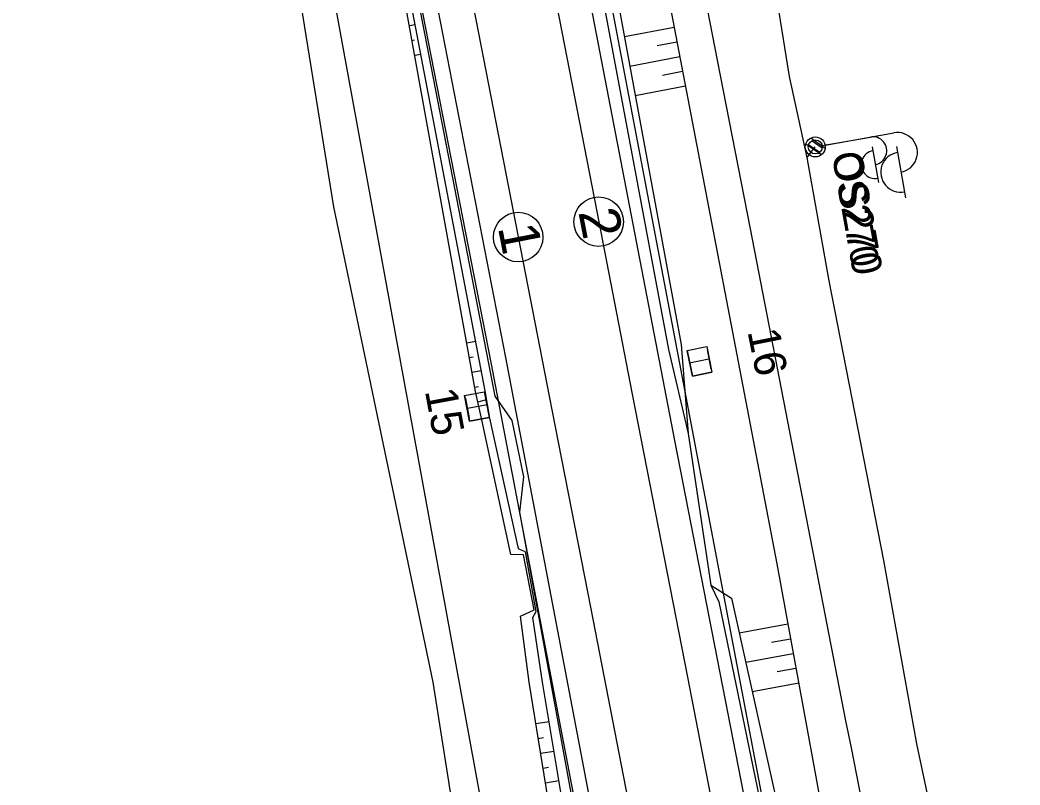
# Model space of a CAD drawing. Extents: x -545967 to -545044, y -1122650 to -1118491.
# Drawn here: x -545852.1 to -545802.1, y -1118662.4 to -1118624.1 of the extents above; entities that cross this region are included whole.
import ezdxf

# ---------------------------------------------------------------- set-up
doc = ezdxf.new("R2010")
doc.units = 0
for name, color, linetype in [('Vrstva 1', 7, 'Continuous'), ('Vrstva 1 - Koleje', 7, 'Continuous'), ('Vrstva 11 - Trakce', 7, 'Continuous'), ('Vrstva 12 - Trakce zaklady', 7, 'Continuous'), ('Vrstva 25', 7, 'Continuous'), ('Vrstva 25 - silnoproud prvky', 7, 'Continuous'), ('Vrstva 26', 7, 'Continuous'), ('Vrstva 26 - silnoproud', 7, 'Continuous'), ('Vrstva 28 - zabzar', 7, 'Continuous'), ('Vrstva 32', 7, 'Continuous'), ('Vrstva 4 - Teren - stezky - prechody - plochy', 7, 'Continuous'), ('Vrstva 44', 7, 'Continuous'), ('Vrstva 48', 7, 'Continuous'), ('Vrstva 49', 7, 'Continuous')]:
    doc.layers.add(name, color=color, linetype=linetype)

msp = doc.modelspace()

# ---------------------------------------------------------------- linework, layer by layer
at = {"layer": 'Vrstva 1'}
msp.add_lwpolyline([(-545825.931, -1118581.521), (-545824.016, -1118591.357), (-545817.098, -1118626.815), (-545815.58, -1118634.584), (-545810.799, -1118659.197), (-545810.531, -1118660.549), (-545805.871, -1118684.414), (-545803.343, -1118697.361)], dxfattribs=at)
at = {"layer": 'Vrstva 1 - Koleje'}
for points in [[(-545844.611, -1118524.236), (-545843.323, -1118530.854), (-545841.995, -1118537.671), (-545840.062, -1118547.589), (-545838.151, -1118557.387), (-545836.187, -1118567.479), (-545834.293, -1118577.171), (-545832.142, -1118588.194), (-545830.344, -1118597.44), (-545828.848, -1118605.077), (-545828.138, -1118608.718), (-545827.12, -1118613.935), (-545825.269, -1118623.436), (-545823.266, -1118633.717), (-545821.486, -1118642.857), (-545818.722, -1118657.024), (-545817.482, -1118663.386), (-545815.845, -1118671.798), (-545813.797, -1118682.286), (-545811.996, -1118691.52), (-545809.67, -1118703.454), (-545807.882, -1118712.632)], [(-545848.628, -1118525.023), (-545847.323, -1118531.712), (-545846.098, -1118538.003), (-545844.166, -1118547.957), (-545842.342, -1118557.292), (-545840.544, -1118566.52), (-545838.785, -1118575.544), (-545836.613, -1118586.684), (-545834.863, -1118595.653), (-545833.089, -1118604.755), (-545832.153, -1118609.557), (-545831.329, -1118613.781), (-545829.452, -1118623.418), (-545827.682, -1118632.501), (-545825.51, -1118643.639), (-545823.563, -1118653.595), (-545821.825, -1118662.539), (-545819.916, -1118672.31), (-545817.993, -1118682.172), (-545816.178, -1118691.474), (-545814.43, -1118700.429), (-545812.52, -1118710.222), (-545810.747, -1118719.317)]]:
    msp.add_lwpolyline(points, dxfattribs=at)
for centre in [(-545823.168, -1118634.223), (-545827.196, -1118634.992)]:
    msp.add_circle(centre, 1.239, dxfattribs=at)
at = {"layer": 'Vrstva 11 - Trakce'}
for p, q in [((-545818.72, -1118640.815), (-545818.524, -1118641.795)), ((-545817.74, -1118640.619), (-545817.544, -1118641.599)), ((-545817.642, -1118641.109), (-545818.622, -1118641.305)), ((-545828.845, -1118642.892), (-545828.662, -1118643.875)), ((-545829.828, -1118643.075), (-545829.645, -1118644.058)), ((-545828.753, -1118643.384), (-545829.737, -1118643.566))]:
    msp.add_line(p, q, dxfattribs=at)
at = {"layer": 'Vrstva 12 - Trakce zaklady'}
for p, q in [((-545818.73, -1118640.671), (-545817.749, -1118640.475)), ((-545818.474, -1118641.954), (-545817.493, -1118641.758)), ((-545829.877, -1118642.92), (-545828.894, -1118642.738))]:
    msp.add_line(p, q, dxfattribs=at)
for points in [[(-545818.474, -1118641.954), (-545818.73, -1118640.671), (-545817.749, -1118640.475), (-545817.493, -1118641.758), (-545818.474, -1118641.954)], [(-545818.73, -1118640.671), (-545818.73, -1118640.671), (-545818.474, -1118641.954), (-545818.474, -1118641.954)], [(-545828.894, -1118642.738), (-545828.655, -1118644.026), (-545829.638, -1118644.208), (-545829.877, -1118642.92), (-545828.894, -1118642.738)], [(-545829.877, -1118642.92), (-545829.877, -1118642.92), (-545829.638, -1118644.208)], [(-545828.894, -1118642.738), (-545828.894, -1118642.738), (-545828.655, -1118644.026), (-545828.655, -1118644.026)], [(-545829.638, -1118644.208), (-545829.638, -1118644.208), (-545828.655, -1118644.026)]]:
    msp.add_lwpolyline(points, dxfattribs=at)
at = {"layer": 'Vrstva 25'}
for p, q in [((-545811.827, -1118630.39), (-545808.382, -1118629.773)), ((-545812.791, -1118630.32), (-545812.006, -1118630.867)), ((-545812.547, -1118630.033), (-545811.825, -1118630.536)), ((-545808.258, -1118630.462), (-545807.8, -1118633.021))]:
    msp.add_line(p, q, dxfattribs=at)
msp.add_circle((-545812.319, -1118630.478), 0.5, dxfattribs=at)
msp.add_circle((-545812.319, -1118630.478), 0.5, dxfattribs=at)
for centre, start, end in [((-545808.205, -1118630.757), 280.1559, 100.1559), ((-545808.041, -1118631.744), 99.4533, 280.8585)]:
    msp.add_arc(centre, 1, start, end, dxfattribs=at)
at = {"layer": 'Vrstva 25 - silnoproud prvky'}
for p, q in [((-545811.974, -1118630.416), (-545809.563, -1118629.984)), ((-545812.65, -1118630.367), (-545812.1, -1118630.75)), ((-545812.479, -1118630.167), (-545811.973, -1118630.518)), ((-545809.476, -1118630.467), (-545809.156, -1118632.258))]:
    msp.add_line(p, q, dxfattribs=at)
msp.add_circle((-545812.319, -1118630.478), 0.35, dxfattribs=at)
for centre, start, end in [((-545809.439, -1118630.673), 280.1559, 100.1559), ((-545809.324, -1118631.364), 99.4533, 280.8585)]:
    msp.add_arc(centre, 0.7, start, end, dxfattribs=at)
at = {"layer": 'Vrstva 26'}
for points in [[(-545795.14, -1118719.856), (-545797.401, -1118709.038), (-545800.896, -1118690.8), (-545801.851, -1118685.761), (-545802.818, -1118681.484), (-545803.86, -1118675.25), (-545805.172, -1118668.631), (-545806.131, -1118665.54), (-545807.231, -1118660.35), (-545808.894, -1118651.177), (-545811.62, -1118637.176), (-545812.724, -1118631.013), (-545813.605, -1118626.947), (-545815.439, -1118615.53)], [(-545812.724, -1118631.013), (-545812.319, -1118630.478)]]:
    msp.add_lwpolyline(points, dxfattribs=at)
at = {"layer": 'Vrstva 26 - silnoproud'}
for points in [[(-545795.14, -1118719.856), (-545797.401, -1118709.038), (-545800.896, -1118690.8), (-545801.851, -1118685.761), (-545802.818, -1118681.484), (-545803.86, -1118675.25), (-545805.172, -1118668.631), (-545806.131, -1118665.54), (-545807.231, -1118660.35), (-545808.894, -1118651.177), (-545811.62, -1118637.176), (-545812.724, -1118631.013), (-545813.605, -1118626.947), (-545815.439, -1118615.53)], [(-545812.724, -1118631.013), (-545812.319, -1118630.478)]]:
    msp.add_lwpolyline(points, dxfattribs=at)
at = {"layer": 'Vrstva 28 - zabzar'}
msp.add_lwpolyline([(-545825.23, -1118696.09), (-545825.619, -1118693.585), (-545825.984, -1118691.226), (-545826.08, -1118690.61), (-545827.72, -1118683.66), (-545828.55, -1118678.72), (-545828.78, -1118674.2), (-545831.46, -1118657.27), (-545836.43, -1118633.48), (-545838.77, -1118619), (-545839.17, -1118613.92), (-545839.25, -1118611.04), (-545838.43, -1118605.08), (-545838.36, -1118603.32)], dxfattribs=at)
at = {"layer": 'Vrstva 32'}
msp.add_lwpolyline([(-545820.43, -1118719.58), (-545822.89, -1118707.67), (-545825.23, -1118696.09), (-545826.08, -1118690.61), (-545827.72, -1118683.66), (-545828.55, -1118678.72), (-545828.78, -1118674.2), (-545831.46, -1118657.27), (-545836.43, -1118633.48), (-545838.77, -1118619)], dxfattribs=at)
at = {"layer": 'Vrstva 4 - Teren - stezky - prechody - plochy'}
for points in [[(-545842.057, -1118523.737), (-545841.08, -1118528.803), (-545840.285, -1118532.869), (-545839.902, -1118534.493), (-545835.95, -1118554.692), (-545830.173, -1118584.852), (-545827.402, -1118599.381), (-545819.669, -1118640.626), (-545818.68, -1118644.829), (-545817.556, -1118652.409), (-545817.153, -1118653.253), (-545814.795, -1118664.646), (-545810.716, -1118686.202), (-545798.466, -1118747.292), (-545787.709, -1118802.92), (-545777.141, -1118857.583)], [(-545842.991, -1118523.919), (-545841.705, -1118530.396), (-545836.849, -1118554.447), (-545831.054, -1118584.604), (-545819.351, -1118645.264), (-545811.232, -1118686.911), (-545799.532, -1118746.647), (-545788.535, -1118802.768), (-545777.847, -1118857.696), (-545765.826, -1118919.341), (-545755.98, -1118970.183), (-545745.509, -1119023.121), (-545734.813, -1119078.883), (-545723.148, -1119138.675), (-545711.327, -1119199.256), (-545707.51, -1119218.932), (-545706.355, -1119218.803)], [(-545711.324, -1119247.435), (-545711.901, -1119243.963), (-545720.224, -1119201.665), (-545721.285, -1119195.757), (-545731.546, -1119141.712), (-545737.081, -1119112.42), (-545743.441, -1119079.103), (-545754.278, -1119022.005), (-545764.127, -1118971.243), (-545774.702, -1118917.119), (-545786.098, -1118858.181), (-545797.005, -1118803.413), (-545807.661, -1118749.422), (-545819.911, -1118686.431), (-545828.531, -1118641.36), (-545850.15, -1118530.525), (-545851.156, -1118525.517)], [(-545710.225, -1119247.22), (-545719.004, -1119201.386), (-545730.622, -1119141.385), (-545736.208, -1119112.206), (-545742.564, -1119078.927), (-545753.414, -1119021.814), (-545763.359, -1118970.942), (-545773.922, -1118916.709), (-545785.328, -1118858.188), (-545796.206, -1118802.914), (-545806.845, -1118748.63), (-545819.206, -1118686.191), (-545827.818, -1118641.013), (-545849.345, -1118530.249), (-545850.409, -1118525.371)]]:
    msp.add_lwpolyline(points, dxfattribs=at)
at = {"layer": 'Vrstva 44'}
for points in [[(-545846.223, -1118571.979), (-545846.221, -1118572.119), (-545836.892, -1118620.467), (-545827.979, -1118669.157), (-545827.809, -1118669.462), (-545827.871, -1118669.728), (-545818.616, -1118716.33), (-545818.55, -1118716.796), (-545818.473, -1118717.196), (-545808.913, -1118765.432), (-545808.826, -1118765.882), (-545808.745, -1118766.383), (-545799.375, -1118814.752), (-545799.301, -1118815.001), (-545799.29, -1118815.321), (-545789.933, -1118863.748)], [(-545823.989, -1118615.966), (-545823.909, -1118616.115), (-545814.588, -1118665.112), (-545823.538, -1118666.512), (-545823.785, -1118666.525)], [(-545833.154, -1118618.242), (-545828.365, -1118642.955), (-545827.522, -1118644.179), (-545826.938, -1118646.983), (-545827.134, -1118648.756), (-545823.92, -1118666.279), (-545823.785, -1118666.525)]]:
    msp.add_lwpolyline(points, dxfattribs=at)
at = {"layer": 'Vrstva 48'}
for p, q in [((-545832.646, -1118624.41), (-545832.358, -1118624.358)), ((-545819.385, -1118624.497), (-545821.877, -1118624.973)), ((-545832.513, -1118625.148), (-545832.394, -1118625.127)), ((-545819.245, -1118625.234), (-545820.243, -1118625.425)), ((-545832.379, -1118625.886), (-545832.076, -1118625.831)), ((-545819.104, -1118625.97), (-545821.604, -1118626.449)), ((-545818.963, -1118626.707), (-545819.965, -1118626.899)), ((-545818.822, -1118627.444), (-545821.332, -1118627.924)), ((-545829.777, -1118640.284), (-545829.322, -1118640.202)), ((-545829.643, -1118641.022), (-545829.458, -1118640.988)), ((-545829.51, -1118641.76), (-545829.04, -1118641.675)), ((-545829.377, -1118642.498), (-545829.185, -1118642.463)), ((-545829.219, -1118643.231), (-545828.772, -1118643.128)), ((-545813.695, -1118654.369), (-545816.125, -1118654.816)), ((-545813.56, -1118655.107), (-545814.52, -1118655.284)), ((-545813.424, -1118655.844), (-545815.799, -1118656.282)), ((-545813.288, -1118656.582), (-545814.227, -1118656.755)), ((-545813.152, -1118657.319), (-545815.473, -1118657.747)), ((-545826.312, -1118659.344), (-545825.649, -1118659.237)), ((-545826.192, -1118660.085), (-545825.925, -1118660.042)), ((-545826.072, -1118660.825), (-545825.402, -1118660.717)), ((-545825.952, -1118661.565), (-545825.683, -1118661.522)), ((-545825.833, -1118662.306), (-545825.154, -1118662.196))]:
    msp.add_line(p, q, dxfattribs=at)
at = {"layer": 'Vrstva 49'}
for points in [[(-545839.308, -1118523.198), (-545838.102, -1118529.579), (-545837.4, -1118533.485), (-545832.706, -1118555.695), (-545825.144, -1118594.377), (-545814.251, -1118651.352), (-545808.026, -1118685.152), (-545795.162, -1118750.192), (-545783.943, -1118809.71), (-545774.848, -1118856.951), (-545763.418, -1118915.038), (-545752.928, -1118968.655), (-545741.707, -1119025.946), (-545730.219, -1119081.986), (-545719.001, -1119141.326), (-545708.857, -1119196.833), (-545704.642, -1119214.146)], [(-545841.458, -1118523.619), (-545840.502, -1118528.796), (-545840.206, -1118530.169), (-545839.525, -1118532.718), (-545839.264, -1118534.264), (-545835.124, -1118554.723), (-545829.514, -1118584.885), (-545827.92, -1118592.873), (-545827.648, -1118594.262), (-545826.635, -1118599.217), (-545819.032, -1118640.374), (-545818.68, -1118644.829), (-545817.556, -1118652.409), (-545816.515, -1118653.065), (-545813.954, -1118664.567), (-545810.048, -1118684.976), (-545808.757, -1118691.228), (-545797.462, -1118748.583), (-545796.998, -1118749.953), (-545786.899, -1118802.732), (-545785.57, -1118809.023), (-545776.461, -1118857.744)], [(-545824.16, -1118671.869), (-545825.146, -1118666.549), (-545826.649, -1118657.26), (-545827.074, -1118653.958), (-545826.404, -1118653.648), (-545826.925, -1118650.894), (-545827.565, -1118650.876), (-545829.011, -1118644.138), (-545829.338, -1118642.712), (-545833.54, -1118619.463), (-545834.169, -1118615.67), (-545835.481, -1118612.652), (-545835.879, -1118611.235), (-545835.091, -1118610.526), (-545837.513, -1118600.106), (-545839.838, -1118588.301), (-545840.199, -1118586.919), (-545843.933, -1118569.058), (-545846.959, -1118554.728), (-545851.162, -1118532.2), (-545851.499, -1118530.837), (-545852.142, -1118525.71)], [(-545824.16, -1118671.869), (-545824.439, -1118666.468), (-545825.978, -1118657.274), (-545826.459, -1118654.023), (-545826.289, -1118653.729), (-545826.831, -1118650.738), (-545827.163, -1118650.609), (-545827.191, -1118650.507), (-545828.616, -1118644.06), (-545828.847, -1118642.681), (-545833.279, -1118619.551), (-545834.053, -1118615.548), (-545834.843, -1118612.356), (-545834.941, -1118610.693), (-545837.022, -1118600.001), (-545839.397, -1118588.216), (-545839.769, -1118586.656), (-545843.346, -1118569.094), (-545846.416, -1118554.054), (-545850.693, -1118532.201), (-545850.959, -1118530.818), (-545851.735, -1118525.631)]]:
    msp.add_lwpolyline(points, dxfattribs=at)

# ---------------------------------------------------------------- texts
at = {"layer": 'Vrstva 1 - Koleje'}
for s, p in [('2', (-545824.189, -1118633.73)), ('1', (-545828.217, -1118634.499))]:
    msp.add_text(s, height=2, rotation=281.0347, dxfattribs=at).set_placement(p)
at = {"layer": 'Vrstva 11 - Trakce'}
for s, rotation, p in [('16', 281.2842, (-545815.72, -1118639.712)), ('15', 280.5122, (-545831.873, -1118642.686))]:
    msp.add_text(s, height=1.6, rotation=rotation, dxfattribs=at).set_placement(p)
at = {"layer": 'Vrstva 25'}
msp.add_text('OS270', height=1.5, rotation=280.1559, dxfattribs=at).set_placement((-545811.5, -1118630.839))
at = {"layer": 'Vrstva 25 - silnoproud prvky'}
msp.add_text('OS270', height=1.4, rotation=280.1559, dxfattribs=at).set_placement((-545811.5, -1118630.839))

doc.saveas('drawing.dxf')
